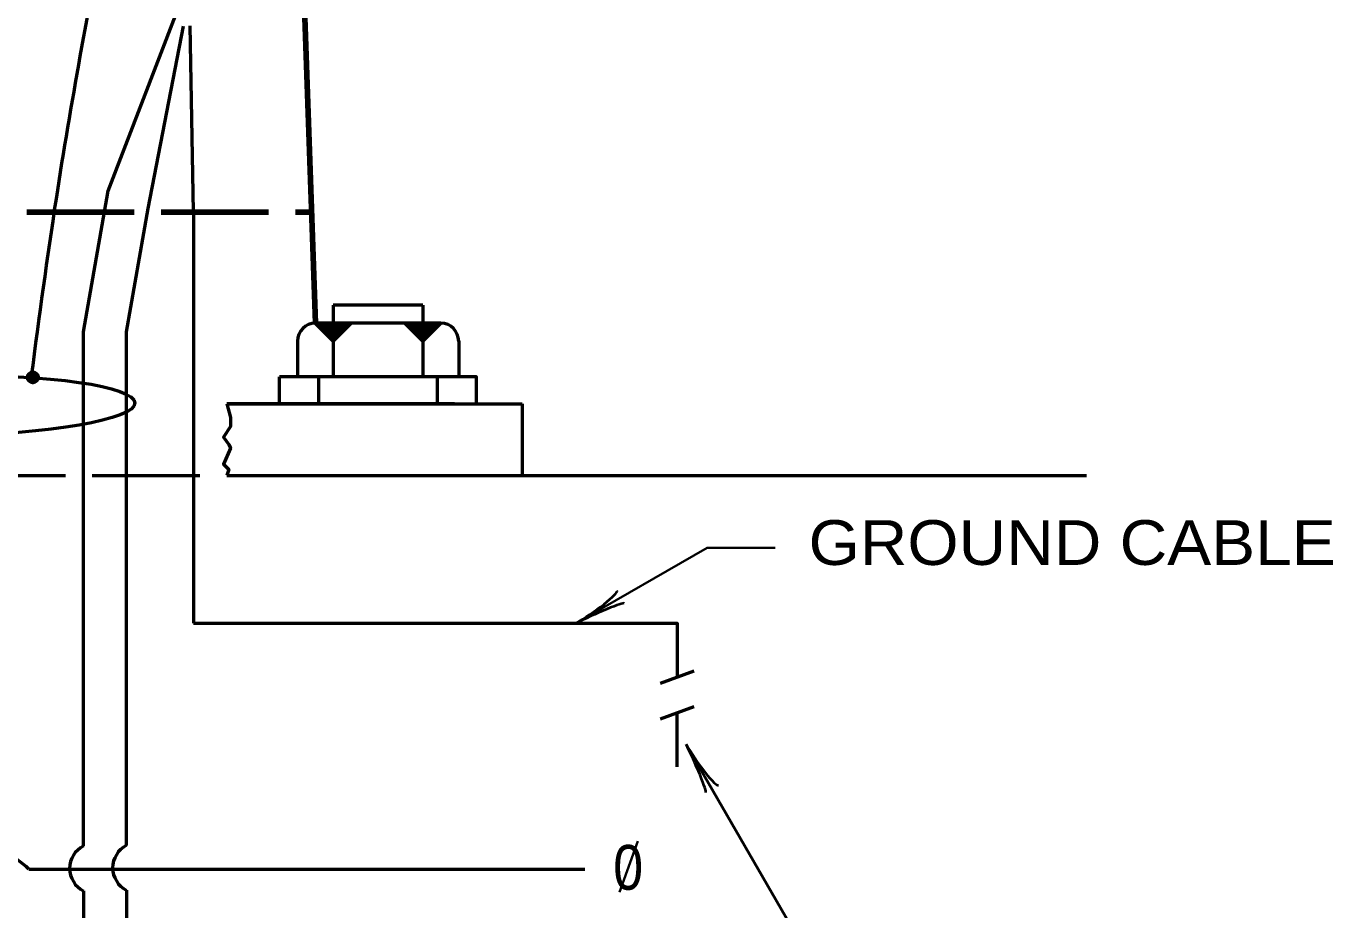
# Model space of a CAD drawing. Extents: x -153 to 527, y -247 to 194.
# Drawn here: x 120.3 to 193.2, y 47.5 to 96.8 of the extents above; entities that cross this region are included whole.
import ezdxf

# ---------------------------------------------------------------- set-up
doc = ezdxf.new("R2010")
doc.units = 0
doc.linetypes.add('LONG_DASHED', pattern=[7.5, 6, -1.5])
doc.layers.add('1', color=7, linetype='Continuous', lineweight=53)

msp = doc.modelspace()

# ---------------------------------------------------------------- linework, layer by layer
at = {"layer": '1', "lineweight": 90}
msp.add_line((136.438, 80.231), (133.611, 161.182), dxfattribs=at)
at = {"layer": '1'}
for p, q in [((124.878, 87.628), (128.635, 97.416)), ((127.104, 86.643), (129.081, 96.814)), ((129.637, 86.475), (129.457, 96.835)), ((123.488, 79.749), (124.878, 87.628)), ((125.888, 79.749), (127.104, 86.643)), ((129.637, 86.475), (129.637, 63.475)), ((137.438, 81.231), (137.438, 77.231)), ((142.438, 81.231), (137.438, 81.231)), ((142.438, 81.231), (142.438, 77.231)), ((137.665, 79.462), (136.892, 80.234)), ((123.488, 51.028), (123.488, 79.749)), ((125.888, 51.059), (125.888, 79.749)), ((137.431, 79.228), (136.431, 80.228)), ((143.438, 80.231), (136.438, 80.231)), ((137.438, 79.231), (136.438, 80.231)), ((137.445, 79.243), (136.46, 80.228)), ((137.458, 79.255), (136.482, 80.231)), ((137.458, 79.255), (136.485, 80.228)), ((137.47, 79.268), (136.51, 80.228)), ((137.483, 79.28), (136.535, 80.228)), ((137.489, 79.286), (136.548, 80.228)), ((137.492, 79.289), (136.55, 80.231)), ((137.503, 79.3), (136.572, 80.231)), ((137.505, 79.302), (136.579, 80.228)), ((137.506, 79.304), (136.582, 80.228)), ((137.517, 79.315), (136.604, 80.228)), ((137.484, 79.282), (136.612, 80.154)), ((137.522, 79.319), (136.613, 80.228)), ((137.5, 79.297), (136.628, 80.17)), ((137.505, 79.302), (136.632, 80.174)), ((137.506, 79.303), (136.634, 80.176)), ((137.506, 79.303), (136.634, 80.176)), ((137.533, 79.331), (136.636, 80.228)), ((137.514, 79.311), (136.642, 80.184)), ((137.519, 79.316), (136.646, 80.188)), ((137.541, 79.338), (136.651, 80.228)), ((137.524, 79.321), (136.651, 80.193)), ((137.542, 79.34), (136.654, 80.228)), ((137.544, 79.341), (136.672, 80.213)), ((137.553, 79.351), (136.681, 80.223)), ((137.556, 79.354), (136.684, 80.226)), ((137.558, 79.356), (136.686, 80.228)), ((137.566, 79.363), (136.698, 80.231)), ((137.569, 79.366), (136.707, 80.228)), ((137.578, 79.376), (136.726, 80.228)), ((137.589, 79.387), (136.745, 80.231)), ((137.591, 79.388), (136.751, 80.228)), ((137.594, 79.391), (136.758, 80.228)), ((137.599, 79.396), (136.767, 80.228)), ((137.607, 79.404), (136.779, 80.231)), ((137.608, 79.406), (136.786, 80.228)), ((137.619, 79.416), (136.804, 80.231)), ((137.621, 79.418), (136.811, 80.228)), ((137.625, 79.423), (136.817, 80.231)), ((137.624, 79.421), (136.817, 80.228)), ((137.635, 79.432), (136.839, 80.228)), ((137.644, 79.441), (136.855, 80.231)), ((137.65, 79.448), (136.867, 80.231)), ((137.655, 79.453), (136.877, 80.231)), ((137.66, 79.457), (136.886, 80.231)), ((137.659, 79.456), (136.886, 80.228)), ((137.663, 79.46), (136.896, 80.228)), ((137.674, 79.471), (136.914, 80.231)), ((137.674, 79.471), (136.914, 80.231)), ((137.673, 79.47), (136.914, 80.228)), ((137.68, 79.478), (136.927, 80.231)), ((137.687, 79.484), (136.939, 80.231)), ((137.696, 79.493), (136.958, 80.231)), ((137.697, 79.495), (136.961, 80.231)), ((137.702, 79.499), (136.97, 80.231)), ((137.709, 79.506), (136.986, 80.228)), ((137.713, 79.51), (136.993, 80.231)), ((137.721, 79.519), (137.012, 80.228)), ((137.726, 79.523), (137.017, 80.231)), ((137.669, 79.466), (137.019, 80.116)), ((137.732, 79.529), (137.034, 80.228)), ((137.696, 79.493), (137.046, 80.143)), ((137.704, 79.501), (137.054, 80.151)), ((137.721, 79.518), (137.071, 80.168)), ((137.759, 79.556), (137.087, 80.228)), ((137.738, 79.535), (137.088, 80.185)), ((137.76, 79.557), (137.11, 80.207)), ((137.77, 79.567), (137.12, 80.217)), ((137.774, 79.572), (137.124, 80.221)), ((137.781, 79.578), (137.131, 80.228)), ((137.788, 79.586), (137.143, 80.231)), ((137.79, 79.587), (137.149, 80.228)), ((137.796, 79.594), (137.162, 80.228)), ((137.804, 79.601), (137.174, 80.231)), ((137.804, 79.601), (137.174, 80.231)), ((137.812, 79.609), (137.19, 80.231)), ((137.82, 79.617), (137.206, 80.231)), ((137.821, 79.619), (137.209, 80.231)), ((137.823, 79.62), (137.215, 80.228)), ((137.826, 79.623), (137.218, 80.231)), ((137.826, 79.623), (137.218, 80.231)), ((137.832, 79.63), (137.231, 80.231)), ((137.831, 79.628), (137.231, 80.228)), ((137.837, 79.634), (137.24, 80.231)), ((137.846, 79.644), (137.259, 80.231)), ((137.847, 79.644), (137.263, 80.228)), ((137.854, 79.651), (137.275, 80.231)), ((137.862, 79.659), (137.294, 80.228)), ((137.889, 79.686), (137.347, 80.228)), ((137.898, 79.695), (137.363, 80.231)), ((137.908, 79.705), (137.381, 80.231)), ((137.909, 79.706), (137.384, 80.231)), ((137.431, 79.228), (138.431, 80.228)), ((137.438, 79.231), (138.438, 80.231)), ((137.934, 79.732), (137.438, 80.228)), ((137.934, 79.732), (137.438, 80.228)), ((137.945, 79.743), (137.457, 80.231)), ((137.947, 79.744), (137.468, 80.223)), ((137.952, 79.749), (137.472, 80.228)), ((137.955, 79.752), (137.475, 80.231)), ((137.958, 79.755), (137.482, 80.231)), ((137.961, 79.758), (137.488, 80.231)), ((137.967, 79.764), (137.501, 80.231)), ((137.975, 79.772), (137.516, 80.231)), ((137.981, 79.779), (137.532, 80.228)), ((137.988, 79.785), (137.541, 80.231)), ((137.994, 79.791), (137.557, 80.228)), ((137.999, 79.796), (137.563, 80.231)), ((138.01, 79.807), (137.589, 80.228)), ((138.02, 79.818), (137.61, 80.228)), ((138.024, 79.821), (137.613, 80.231)), ((138.031, 79.829), (137.629, 80.231)), ((138.047, 79.844), (137.664, 80.228)), ((138.066, 79.863), (137.698, 80.231)), ((138.064, 79.862), (137.698, 80.228)), ((138.069, 79.866), (137.707, 80.228)), ((138.072, 79.87), (137.711, 80.231)), ((138.078, 79.876), (137.723, 80.231)), ((138.082, 79.879), (137.729, 80.231)), ((138.089, 79.887), (137.745, 80.231)), ((137.84, 79.637), (137.758, 79.719)), ((138.104, 79.901), (137.773, 80.231)), ((138.064, 79.862), (137.775, 80.151)), ((138.111, 79.909), (137.789, 80.231)), ((138.123, 79.92), (137.811, 80.231)), ((137.904, 79.701), (137.822, 79.784)), ((138.141, 79.938), (137.849, 80.231)), ((138.148, 79.945), (137.861, 80.231)), ((138.152, 79.949), (137.874, 80.228)), ((137.958, 79.754), (137.875, 79.837)), ((137.975, 79.772), (137.892, 79.854)), ((138.179, 79.976), (137.927, 80.228)), ((138.017, 79.814), (137.935, 79.897)), ((138.19, 79.987), (137.949, 80.228)), ((138.21, 80.007), (137.99, 80.228)), ((138.08, 79.877), (137.997, 79.959)), ((138.223, 80.02), (138.015, 80.228)), ((138.23, 80.027), (138.026, 80.231)), ((138.235, 80.032), (138.037, 80.231)), ((138.238, 80.036), (138.043, 80.231)), ((138.153, 79.95), (138.071, 80.033)), ((138.273, 80.07), (138.115, 80.228)), ((138.279, 80.076), (138.124, 80.231)), ((138.299, 80.097), (138.165, 80.231)), ((138.265, 80.062), (138.182, 80.144)), ((138.276, 80.073), (138.193, 80.155)), ((138.31, 80.107), (138.227, 80.19)), ((138.315, 80.112), (138.232, 80.194)), ((138.336, 80.133), (138.237, 80.231)), ((138.325, 80.122), (138.242, 80.204)), ((138.328, 80.125), (138.245, 80.207)), ((138.348, 80.145), (138.266, 80.228)), ((138.351, 80.148), (138.269, 80.231)), ((138.356, 80.153), (138.278, 80.231)), ((138.365, 80.163), (138.297, 80.231)), ((138.419, 80.216), (138.404, 80.231)), ((142.438, 79.231), (141.438, 80.231)), ((142.452, 79.246), (141.467, 80.231)), ((142.465, 79.258), (141.492, 80.231)), ((142.465, 79.258), (141.492, 80.231)), ((142.477, 79.271), (141.517, 80.231)), ((142.49, 79.283), (141.542, 80.231)), ((142.496, 79.29), (141.554, 80.231)), ((142.512, 79.305), (141.586, 80.231)), ((142.513, 79.307), (141.589, 80.231)), ((142.524, 79.318), (141.611, 80.231)), ((142.529, 79.322), (141.62, 80.231)), ((142.54, 79.334), (141.642, 80.231)), ((142.54, 79.334), (141.643, 80.231)), ((142.548, 79.341), (141.658, 80.231)), ((142.549, 79.343), (141.661, 80.231)), ((142.559, 79.352), (141.68, 80.231)), ((142.562, 79.355), (141.686, 80.231)), ((142.565, 79.359), (141.693, 80.231)), ((142.585, 79.379), (141.733, 80.231)), ((142.598, 79.391), (141.758, 80.231)), ((142.606, 79.399), (141.774, 80.231)), ((142.615, 79.409), (141.793, 80.231)), ((142.628, 79.421), (141.818, 80.231)), ((142.642, 79.435), (141.846, 80.231)), ((142.65, 79.443), (141.862, 80.231)), ((142.656, 79.45), (141.874, 80.231)), ((142.665, 79.459), (141.893, 80.231)), ((142.67, 79.464), (141.903, 80.231)), ((142.679, 79.473), (141.921, 80.231)), ((142.686, 79.479), (141.934, 80.231)), ((142.697, 79.49), (141.956, 80.231)), ((142.715, 79.509), (141.993, 80.231)), ((142.725, 79.518), (142.012, 80.231)), ((142.728, 79.522), (142.018, 80.231)), ((142.728, 79.522), (142.019, 80.231)), ((142.739, 79.533), (142.04, 80.231)), ((142.747, 79.54), (142.056, 80.231)), ((142.761, 79.555), (142.084, 80.231)), ((142.766, 79.559), (142.094, 80.231)), ((142.778, 79.572), (142.119, 80.231)), ((142.788, 79.581), (142.138, 80.231)), ((142.797, 79.59), (142.156, 80.231)), ((142.803, 79.597), (142.169, 80.231)), ((142.805, 79.598), (142.172, 80.231)), ((142.83, 79.623), (142.222, 80.231)), ((142.838, 79.631), (142.238, 80.231)), ((142.844, 79.638), (142.25, 80.231)), ((142.85, 79.644), (142.263, 80.231)), ((142.85, 79.644), (142.263, 80.231)), ((142.853, 79.647), (142.269, 80.231)), ((142.853, 79.647), (142.269, 80.231)), ((142.858, 79.652), (142.279, 80.231)), ((142.869, 79.663), (142.301, 80.231)), ((142.896, 79.689), (142.354, 80.231)), ((142.907, 79.7), (142.376, 80.231)), ((142.915, 79.708), (142.391, 80.231)), ((142.438, 79.231), (143.438, 80.231)), ((142.941, 79.735), (142.445, 80.231)), ((142.941, 79.735), (142.445, 80.231)), ((142.946, 79.739), (142.454, 80.231)), ((142.952, 79.746), (142.467, 80.231)), ((142.955, 79.749), (142.473, 80.231)), ((142.958, 79.752), (142.479, 80.231)), ((142.962, 79.755), (142.486, 80.231)), ((142.988, 79.782), (142.539, 80.231)), ((143.001, 79.794), (142.564, 80.231)), ((143.007, 79.801), (142.576, 80.231)), ((143.01, 79.804), (142.583, 80.231)), ((142.672, 79.464), (142.589, 79.547)), ((143.017, 79.81), (142.595, 80.231)), ((143.021, 79.815), (142.605, 80.231)), ((143.027, 79.821), (142.617, 80.231)), ((143.032, 79.826), (142.627, 80.231)), ((143.054, 79.848), (142.671, 80.231)), ((142.761, 79.554), (142.678, 79.636)), ((143.071, 79.865), (142.705, 80.231)), ((143.076, 79.87), (142.714, 80.231)), ((143.081, 79.874), (142.724, 80.231)), ((142.847, 79.64), (142.764, 79.723)), ((142.859, 79.653), (142.777, 79.735)), ((143.11, 79.904), (142.783, 80.231)), ((142.88, 79.673), (142.797, 79.755)), ((143.118, 79.912), (142.799, 80.231)), ((142.883, 79.676), (142.801, 79.759)), ((143.129, 79.923), (142.821, 80.231)), ((143.131, 79.924), (142.824, 80.231)), ((142.911, 79.704), (142.829, 79.787)), ((142.914, 79.708), (142.832, 79.79)), ((142.941, 79.734), (142.858, 79.817)), ((143.148, 79.942), (142.859, 80.231)), ((142.949, 79.742), (142.866, 79.825)), ((143.159, 79.953), (142.88, 80.231)), ((142.964, 79.758), (142.882, 79.84)), ((142.982, 79.775), (142.899, 79.857)), ((143.186, 79.979), (142.934, 80.231)), ((143.024, 79.817), (142.941, 79.9)), ((143.217, 80.011), (142.997, 80.231)), ((143.087, 79.88), (143.004, 79.962)), ((143.222, 80.015), (143.006, 80.231)), ((143.23, 80.023), (143.022, 80.231)), ((143.234, 80.028), (143.031, 80.231)), ((143.138, 79.932), (143.056, 80.014)), ((143.256, 80.05), (143.075, 80.231)), ((143.189, 79.982), (143.106, 80.064)), ((143.28, 80.073), (143.122, 80.231)), ((143.22, 80.013), (143.137, 80.096)), ((143.257, 80.051), (143.175, 80.133)), ((143.272, 80.065), (143.189, 80.147)), ((143.282, 80.076), (143.2, 80.158)), ((143.317, 80.11), (143.234, 80.193)), ((143.322, 80.115), (143.239, 80.198)), ((143.325, 80.118), (143.242, 80.201)), ((143.342, 80.135), (143.259, 80.218)), ((143.355, 80.149), (143.272, 80.231)), ((143.397, 80.19), (143.357, 80.231)), ((143.405, 80.198), (143.371, 80.232)), ((143.411, 80.204), (143.385, 80.23)), ((143.417, 80.211), (143.4, 80.228)), ((135.438, 79.231), (135.438, 77.231)), ((137.558, 79.355), (137.476, 79.437)), ((137.594, 79.391), (137.512, 79.473)), ((142.535, 79.328), (142.453, 79.411)), ((142.601, 79.394), (142.518, 79.476)), ((144.438, 79.231), (144.438, 77.231)), ((134.438, 75.731), (134.438, 77.231)), ((136.635, 75.731), (136.635, 77.231)), ((143.247, 75.731), (143.247, 77.231)), ((131.488, 75.731), (147.988, 75.731)), ((144.196, 75.731), (131.488, 75.731)), ((147.988, 75.731), (147.988, 71.731)), ((131.488, 71.731), (179.488, 71.731)), ((155.698, 60.133), (157.577, 60.817)), ((155.698, 58.133), (157.577, 58.817)), ((156.622, 58.451), (156.622, 55.451)), ((120.438, 49.731), (151.488, 49.731)), ((123.488, 48.528), (123.488, 45.026)), ((125.888, 48.559), (125.888, 45.045))]:
    msp.add_line(p, q, dxfattribs=at)
at = {"layer": '1', "linetype": 'LONG_DASHED', "lineweight": 90}
msp.add_line((90.328, 86.427), (136.109, 86.427), dxfattribs=at)
at = {"layer": '1', "linetype": 'LONG_DASHED'}
msp.add_line((93.988, 71.731), (131.488, 71.731), dxfattribs=at)
at = {"layer": '1', "lineweight": 35}
msp.add_line((154.437, 51.293), (153.406, 48.46), dxfattribs=at)
at = {"layer": '1'}
for points in [[(145.438, 75.731), (145.438, 77.231), (134.438, 77.231)], [(131.488, 75.731), (131.707, 74.962), (131.707, 74.46), (131.305, 73.858), (131.606, 73.456), (131.707, 73.255), (131.305, 72.352), (131.606, 72.051), (131.488, 71.731)], [(129.637, 63.475), (156.637, 63.475), (156.637, 60.475)]]:
    msp.add_lwpolyline(points, dxfattribs=at)
at = {"layer": '1', "lineweight": 35}
for points in [[(162.101, 67.692), (158.302, 67.692), (150.998, 63.475)], [(168.487, 43.604), (164.689, 43.604), (157.127, 56.701)]]:
    msp.add_lwpolyline(points, dxfattribs=at)
at = {"layer": '1'}
for centre, radius in [((120.668, 77.206), 0.3), ((120.656, 77.215), 0.277), ((120.659, 77.209), 0.248), ((120.646, 77.212), 0.217), ((120.659, 77.199), 0.211), ((120.665, 77.228), 0.203), ((120.656, 77.228), 0.174), ((120.647, 77.234), 0.143), ((120.656, 77.237), 0.117), ((120.647, 77.278), 0.0659), ((120.665, 77.243), 0.0813), ((120.643, 77.328), 0.0565), ((120.675, 77.297), 0.0715), ((120.775, 77.287), 0.0313), ((120.512, 77.203), 0.0536), ((120.631, 77.206), 0.0836), ((120.584, 77.08), 0.0309), ((120.64, 77.231), 0.0745), ((120.637, 77.24), 0.0201), ((120.694, 77.071), 0.069), ((120.678, 77.234), 0.0399), ((120.703, 77.055), 0.0129), ((120.7, 77.077), 0.007), ((120.722, 77.096), 0.0239), ((120.753, 77.206), 0.0157), ((120.831, 77.174), 0.0401), ((120.853, 77.246), 0.0133)]:
    msp.add_circle(centre, radius, dxfattribs=at)
for centre, radius, start, end in [((136.438, 79.231), 1, 90, 180), ((143.438, 79.231), 1, 0, 90), ((126.525, 49.809), 1.403, 116.97883, 243.02117), ((117.438, 46.802), 4.193, 44.31179, 135.71806), ((124.125, 49.778), 1.403, 116.97883, 243.02117)]:
    msp.add_arc(centre, radius, start, end, dxfattribs=at)
msp.add_ellipse((115.722, 75.62), major_axis=(-10.639, -0.159), ratio=0.158809, dxfattribs=at)
at = {"layer": '1', "lineweight": 40}
for centre, major_axis, ratio, start_param, end_param in [((151.805, 64.26), (-1.468, -1.028), 0.122415, 0.896353, 3.141593), ((152.074, 63.852), (1.609, 0.726), 0.07063, 6.282307, 8.559703), ((157.504, 55.625), (-0.726, 1.609), 0.07063, 3.140715, 5.41811), ((157.912, 55.894), (-1.028, 1.468), 0.122415, 0.896353, 3.141593)]:
    msp.add_ellipse(centre, major_axis=major_axis, ratio=ratio, start_param=start_param, end_param=end_param, dxfattribs=at)
at = {"layer": '1'}
msp.add_spline([(120.597, 77.275), (121.98, 87.17), (124.787, 103.109)], degree=3, dxfattribs=at)

# ---------------------------------------------------------------- texts
for s, width, p in [('GROUND CABLE', 1.1, (163.967, 66.729)), ('0', 0.9, (153.062, 48.588))]:
    msp.add_text(s, height=2.5, dxfattribs=dict(at, width=width)).set_placement(p)

doc.saveas('drawing.dxf')
